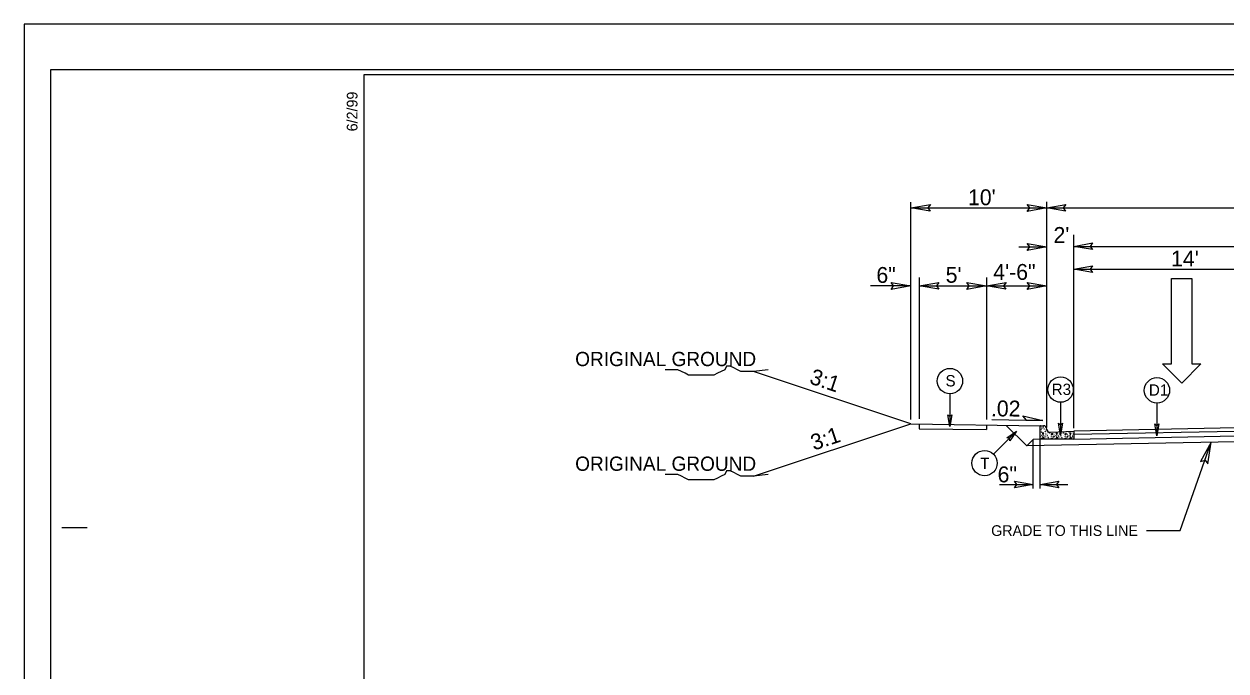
# Model space of a CAD drawing. Extents: x 958711 to 962106, y 831169 to 840840.
# Drawn here: x 958711 to 959301, y 838073 to 838391 of the extents above; entities that cross this region are included whole.
import ezdxf

# ---------------------------------------------------------------- set-up
doc = ezdxf.new("R2010")
doc.units = 0
for name, color, linetype in [('Old_Level_1', 7, 'Continuous'), ('Old_Level_11', 7, 'Continuous'), ('Old_Level_21', 7, 'Continuous'), ('Old_Level_3', 7, 'Continuous'), ('Prop Dimension Text', 7, 'Continuous'), ('Prop Lane Arrow CELL', 7, 'Continuous'), ('Sheet Plot Border Inside CELL', 7, 'Continuous'), ('Sheet Plot Border Outside CELL', 7, 'Continuous'), ('Sheet Typical CELL', 7, 'Continuous'), ('Typical ID Circle CELL', 7, 'Continuous'), ('Typical Terminator CELL', 7, 'Continuous'), ('Typical Text ID Circle CELL', 7, 'Continuous')]:
    doc.layers.add(name, color=color, linetype=linetype)

# ---------------------------------------------------------------- blocks, each defined once
blk = doc.blocks.new('Lane Arrow Through')
at = {"layer": 'Prop Lane Arrow CELL'}
for p, q in [((-3.15, 1.6), (-3.15, 3.1)), ((-3.15, 3.1), (0, 0)), ((-17.15, 1.6), (-3.15, 1.6)), ((-17.15, -1.7), (-17.15, 1.6)), ((0, 0), (-3.15, -3.2)), ((-3.15, -1.7), (-17.15, -1.7)), ((-3.15, -3.2), (-3.15, -1.7))]:
    blk.add_line(p, q, dxfattribs=at)

msp = doc.modelspace()

# ---------------------------------------------------------------- linework, layer by layer
at = {"layer": 'Old_Level_1'}
for p, q in [((959146.5, 838196.74), (959146.5, 838303.59)), ((959146.5, 838300.69), (959213.41, 838300.69)), ((959213.41, 838192.71), (959213.41, 838303.63)), ((959213.41, 838300.69), (959779.86, 838300.69)), ((959226.62, 838192.47), (959226.62, 838287.45)), ((959199.59, 838281.53), (959213.41, 838281.53)), ((959226.62, 838281.8), (959426.79, 838281.8)), ((959150.68, 838266.52), (959150.68, 838196.95)), ((959183.7, 838266.52), (959183.7, 838196.73)), ((959226.62, 838270.55), (959333.31, 838270.55)), ((959146.5, 838262.35), (959126.71, 838262.35)), ((959150.68, 838262.35), (959183.7, 838262.35)), ((959183.7, 838262.35), (959213.41, 838262.35)), ((959146.5, 838194.56), (959069.31, 838220.29)), ((959069.31, 838168.83), (959146.5, 838194.56)), ((959146.5, 838194.56), (959210.34, 838193.62)), ((959150.68, 838194.5), (959150.68, 838192.04)), ((959186.41, 838196.65), (959211.39, 838196.15)), ((959494.95, 838196.39), (959226.62, 838190.96)), ((959150.68, 838192.04), (959183.7, 838191.71)), ((959183.7, 838194.01), (959183.7, 838191.71)), ((959203.5, 838183.67), (959193.39, 838193.79)), ((959332.23, 838191.37), (959226.62, 838189.24)), ((959332.23, 838188.95), (959226.62, 838186.81)), ((959206.75, 838186.92), (959203.5, 838183.67)), ((959332.23, 838186.28), (959203.5, 838183.67)), ((959210.05, 838186.98), (959206.75, 838186.92)), ((959206.75, 838162.76), (959206.75, 838186.72)), ((959210.05, 838162.76), (959210.05, 838186.72)), ((959278.98, 838142.19), (959294.19, 838185.51)), ((959190.15, 838164.72), (959206.75, 838164.72)), ((959210.05, 838164.72), (959223.78, 838164.72)), ((959262.36, 838142.19), (959278.98, 838142.19))]:
    msp.add_line(p, q, dxfattribs=at)
at = {"layer": 'Old_Level_11'}
for p, q in [((959203.38, 838196.31), (959201.65, 838198.57)), ((959201.65, 838198.57), (959211.39, 838196.15)), ((959211.39, 838196.15), (959203.38, 838196.31))]:
    msp.add_line(p, q, dxfattribs=at)
for points in [[(959156.1, 838299.03), (959146.5, 838300.69), (959156.16, 838302.39), (959154.94, 838300.69)], [(959203.81, 838302.34), (959213.41, 838300.69), (959203.75, 838298.97), (959204.98, 838300.69)], [(959203.81, 838283.19), (959213.41, 838281.53), (959203.75, 838279.81), (959204.98, 838281.53)], [(959136.89, 838264), (959146.5, 838262.35), (959136.83, 838260.63), (959138.06, 838262.35)], [(959160.28, 838260.69), (959150.68, 838262.35), (959160.34, 838264.06), (959159.12, 838262.35)], [(959174.09, 838264), (959183.7, 838262.35), (959174.03, 838260.63), (959175.26, 838262.35)], [(959193.3, 838260.69), (959183.7, 838262.35), (959193.36, 838264.06), (959192.13, 838262.35)], [(959203.81, 838264), (959213.41, 838262.35), (959203.75, 838260.63), (959204.98, 838262.35)], [(959292.49, 838174.91), (959294.19, 838185.51), (959288.98, 838176.05), (959291.18, 838176.73)]]:
    msp.add_lwpolyline(points, close=True, dxfattribs=at)
at = {"layer": 'Old_Level_21'}
for points in [[(959076.4, 838221.17), (959069.31, 838220.29), (959067.53, 838220.29), (959064.88, 838220.29), (959063.1, 838220.29), (959061.33, 838221.17), (959059.55, 838222.07), (959057.78, 838222.95), (959056, 838222.95), (959055.11, 838221.17), (959053.35, 838220.29), (959051.57, 838219.4), (959049.8, 838218.52), (959048.02, 838218.52), (959046.25, 838218.52), (959044.48, 838218.52), (959042.71, 838218.52), (959040.93, 838218.52), (959039.16, 838218.52), (959037.38, 838218.52), (959035.61, 838219.4), (959033.84, 838220.29), (959032.07, 838221.17), (959029.4, 838221.17), (959027.63, 838221.17), (959025.85, 838221.17)], [(959076.4, 838169.71), (959069.31, 838168.83), (959067.53, 838168.83), (959064.88, 838168.83), (959063.1, 838168.83), (959061.33, 838169.71), (959059.55, 838170.61), (959057.78, 838171.49), (959056, 838171.49), (959055.11, 838169.71), (959053.35, 838168.83), (959051.57, 838167.93), (959049.8, 838167.06), (959048.02, 838167.06), (959046.25, 838167.06), (959044.48, 838167.06), (959042.71, 838167.06), (959040.93, 838167.06), (959039.16, 838167.06), (959037.38, 838167.06), (959035.61, 838167.93), (959033.84, 838168.83), (959032.07, 838169.71), (959029.4, 838169.71), (959027.63, 838169.71), (959025.85, 838169.71)]]:
    msp.add_lwpolyline(points, dxfattribs=at)
at = {"layer": 'Old_Level_3'}
for p, q in [((959210.05, 838190.3), (959210.05, 838193.33)), ((959210.05, 838186.98), (959210.05, 838190.3)), ((959210.34, 838193.62), (959211.71, 838193.62)), ((959211.32, 838190.07), (959211.32, 838189.49)), ((959211.91, 838190.04), (959211.32, 838190.07)), ((959211.32, 838189.49), (959211.91, 838190.04)), ((959213.5, 838191.57), (959213.39, 838191.42)), ((959213.39, 838191.42), (959213.53, 838191.46)), ((959215.08, 838190.39), (959226.62, 838190.96)), ((959215.08, 838190.39), (959215.08, 838190.39)), ((959215.54, 838189.66), (959215.63, 838189.18)), ((959216.37, 838189.43), (959215.54, 838189.66)), ((959215.63, 838189.18), (959216.37, 838189.43)), ((959218.05, 838190.07), (959218.05, 838189.49)), ((959218.64, 838190.04), (959218.05, 838190.07)), ((959218.05, 838189.49), (959218.64, 838190.04)), ((959222.27, 838189.66), (959222.37, 838189.18)), ((959223.1, 838189.43), (959222.27, 838189.66)), ((959222.37, 838189.18), (959223.1, 838189.43)), ((959224.78, 838190.07), (959224.78, 838189.49)), ((959225.36, 838190.04), (959224.78, 838190.07)), ((959224.78, 838189.49), (959225.36, 838190.04)), ((959226.62, 838190.96), (959226.62, 838186.98)), ((959226.62, 838186.98), (959210.05, 838186.98)), ((959211.24, 838187.37), (959211.7, 838188.02)), ((959211.87, 838187.4), (959211.24, 838187.37)), ((959211.7, 838188.02), (959211.87, 838187.4)), ((959215.35, 838187.1), (959215.69, 838187.71)), ((959216.25, 838187.31), (959215.35, 838187.1)), ((959215.69, 838187.71), (959216.25, 838187.31)), ((959217.97, 838187.37), (959218.43, 838188.02)), ((959218.6, 838187.4), (959217.97, 838187.37)), ((959218.43, 838188.02), (959218.6, 838187.4)), ((959222.08, 838187.1), (959222.42, 838187.71)), ((959222.98, 838187.31), (959222.08, 838187.1)), ((959222.42, 838187.71), (959222.98, 838187.31)), ((959224.69, 838187.37), (959225.15, 838188.02)), ((959225.34, 838187.4), (959224.69, 838187.37)), ((959225.15, 838188.02), (959225.34, 838187.4))]:
    msp.add_line(p, q, dxfattribs=at)
for centre in [(959210.11, 838191.88), (959210.2, 838189.3), (959210.74, 838190.5), (959210.87, 838191.79), (959210.9, 838188.9), (959211.02, 838192.53), (959211.42, 838188.44), (959211.67, 838188.99), (959211.88, 838192.9), (959212.04, 838191.98), (959212.47, 838188.65), (959212.68, 838190.69), (959212.96, 838189.58), (959212.99, 838192.78), (959213.02, 838191.48), (959213.57, 838188.57), (959213.67, 838188.84), (959213.7, 838189.64), (959213.79, 838190.65), (959214.77, 838190.04), (959215.05, 838188.69), (959215.7, 838188.41), (959216.22, 838189.88), (959216.74, 838188.41), (959216.93, 838189.3), (959217.63, 838188.9), (959218.15, 838188.44), (959218.39, 838188.99), (959219.19, 838188.65), (959219.69, 838189.58), (959220.3, 838188.57), (959220.39, 838188.84), (959220.43, 838189.64), (959221.5, 838190.04), (959221.78, 838188.69), (959222.42, 838188.41), (959222.95, 838189.88), (959223.47, 838188.41), (959223.66, 838189.3), (959224.2, 838190.5), (959224.35, 838188.9), (959224.88, 838188.44), (959225.12, 838188.99), (959225.92, 838188.65), (959226.14, 838190.69), (959226.42, 838189.58), (959210.23, 838187.12), (959210.31, 838188.23), (959210.74, 838187.37), (959212.62, 838188.11), (959213.42, 838187.65), (959214.1, 838187.8), (959216.65, 838187.89), (959216.96, 838187.12), (959217.04, 838188.23), (959217.47, 838187.37), (959219.35, 838188.11), (959220.15, 838187.65), (959220.83, 838187.8), (959223.38, 838187.89), (959223.69, 838187.12), (959223.77, 838188.23), (959224.2, 838187.37), (959226.08, 838188.11)]:
    msp.add_circle(centre, 0.0432, dxfattribs=at)
for centre, radius, start, end in [((959210.34, 838193.33), 0.287, 90, 180), ((959210.23, 838193.55), 0.0432, 259.65309, 10.34691), ((959211.71, 838191.96), 1.66, 1.07335, 90), ((959215, 838192.02), 1.64, 181.07335, 272.86241), ((959217.47, 838190.5), 0.0432, 167.77954, 17.93798), ((959220.52, 838190.65), 0.0432, 169.83737, 15.88014), ((959210.01, 838188.41), 0.0432, 330.41728, 29.58272)]:
    msp.add_arc(centre, radius, start, end, dxfattribs=at)
at = {"layer": 'Sheet Plot Border Inside CELL'}
msp.add_lwpolyline([(960390.3, 838368.62), (958723.8, 838368.62), (958723.8, 837313.52), (960390.3, 837313.52)], close=True, dxfattribs=at)
at = {"layer": 'Sheet Plot Border Outside CELL'}
msp.add_lwpolyline([(960394.8, 838391.07), (958710.8, 838391.07), (958710.8, 837291.07), (960394.8, 837291.07)], close=True, dxfattribs=at)
at = {"layer": 'Sheet Typical CELL'}
msp.add_line((958729.3, 838143.57), (958741.8, 838143.57), dxfattribs=at)
msp.add_lwpolyline([(960377.8, 838366.07), (958877.8, 838366.07), (958877.8, 837316.07), (960377.8, 837316.07)], close=True, dxfattribs=at)
at = {"layer": 'Typical ID Circle CELL'}
for p, q in [((959165.78, 838209.35), (959165.78, 838193.27)), ((959220.17, 838205.15), (959220.17, 838189.06)), ((959267.53, 838204.8), (959267.53, 838188.71)), ((959187.21, 838179.65), (959198.58, 838191.03))]:
    msp.add_line(p, q, dxfattribs=at)
for centre in [(959165.78, 838215.58), (959220.17, 838211.37), (959267.53, 838211.02), (959182.81, 838175.25)]:
    msp.add_circle(centre, 6.23, dxfattribs=at)
at = {"layer": 'Typical Terminator CELL'}
for points in [[(959222.64, 838299.1), (959213.41, 838300.69), (959222.69, 838302.33), (959221.51, 838300.69)], [(959235.85, 838280.21), (959226.62, 838281.8), (959235.9, 838283.44), (959234.72, 838281.8)], [(959235.85, 838268.97), (959226.62, 838270.55), (959235.9, 838272.19), (959234.72, 838270.55)], [(959166.77, 838199.03), (959165.78, 838193.27), (959164.75, 838199.06), (959165.78, 838198.32)], [(959221.16, 838194.83), (959220.17, 838189.06), (959219.15, 838194.86), (959220.17, 838194.12)], [(959268.52, 838194.48), (959267.53, 838188.71), (959266.5, 838194.51), (959267.53, 838193.77)], [(959193.8, 838187.65), (959198.58, 838191.03), (959195.21, 838186.2), (959195, 838187.45)], [(959197.52, 838166.31), (959206.75, 838164.72), (959197.47, 838163.08), (959198.65, 838164.72)], [(959219.27, 838163.13), (959210.05, 838164.72), (959219.32, 838166.36), (959218.14, 838164.72)]]:
    msp.add_lwpolyline(points, close=True, dxfattribs=at)

# ---------------------------------------------------------------- block references
at = {"layer": 'Old_Level_1', "xscale": 3, "yscale": 3, "rotation": -90.00000000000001}
msp.add_blockref('Lane Arrow Through', (959279.78, 838214.58), dxfattribs=at)

# ---------------------------------------------------------------- texts
at = {"layer": 'Old_Level_1'}
msp.add_text('GRADE TO THIS LINE', height=5.2473, dxfattribs=at).set_placement((959186.05, 838139.46))
at = {"layer": 'Old_Level_21'}
for p in [(958981.63, 838222.92), (958981.63, 838171.46)]:
    msp.add_text('ORIGINAL GROUND', height=7, dxfattribs=at).set_placement(p)
at = {"layer": 'Old_Level_3'}
for s, p in [("10'", (959174.67, 838302.01)), ("2'", (959216.68, 838283.48)), ('6"', (959129.66, 838263.82)), ("5'", (959163.7, 838263.91)), ('4\'-6"', (959187.09, 838265.32))]:
    msp.add_text(s, height=7.801, dxfattribs=at).set_placement(p)
for s, rotation, p in [('3:1', 341.56515, (959096.31, 838214.52)), ('.02', 359.43356, (959185.91, 838198.27)), ('3:1', 18.43485, (959098.9, 838181.35))]:
    msp.add_text(s, height=7.801, rotation=rotation, dxfattribs=at).set_placement(p)
at = {"layer": 'Prop Dimension Text'}
for s, p in [("14'", (959274.48, 838271.91)), ('6"', (959189.22, 838165.8))]:
    msp.add_text(s, height=7.801, rotation=0, dxfattribs=at).set_placement(p)
at = {"layer": 'Sheet Typical CELL'}
msp.add_text('6/2/99', height=5.25, rotation=90, dxfattribs=at).set_placement((958874.65, 838338.32))
at = {"layer": 'Typical Text ID Circle CELL'}
for s, height, p in [('S', 5.57, (959163.61, 838212.95)), ('R3', 5.572, (959215.79, 838208.74)), ('D1', 5.572, (959263.54, 838208.39))]:
    msp.add_text(s, height=height, dxfattribs=at).set_placement(p)
msp.add_text('T', height=5.57, rotation=360, dxfattribs=at).set_placement((959180.65, 838172.35))

doc.saveas('drawing.dxf')
